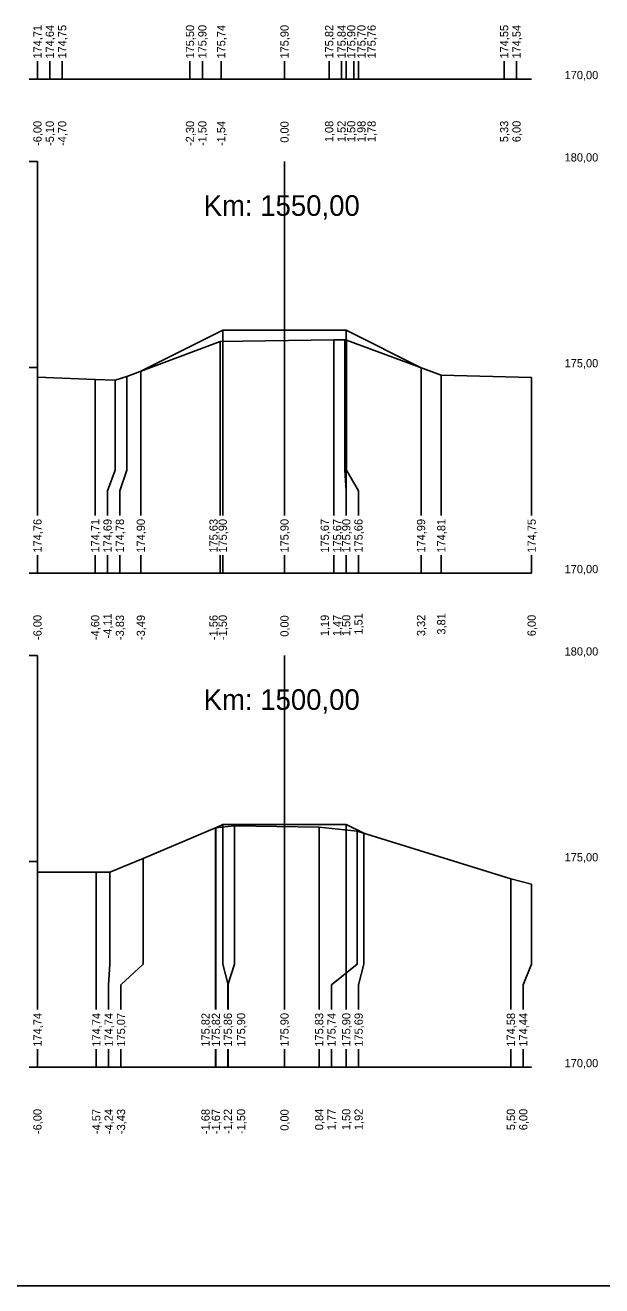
# Model space of a CAD drawing. Extents: x -614174 to -599765, y -1185887 to -1181080.
# Drawn here: x -612606.33 to -612592.33, y -1184252.54 to -1184221.92 of the extents above; entities that cross this region are included whole.
import ezdxf

# ---------------------------------------------------------------- set-up
doc = ezdxf.new("R2010")
doc.units = 0
for name, color, linetype in [('11', 7, 'Continuous'), ('16', 7, 'Continuous'), ('21', 7, 'Continuous'), ('28', 7, 'Continuous'), ('59', 7, 'Continuous'), ('8', 7, 'Continuous'), ('návrh', 7, 'Continuous')]:
    doc.layers.add(name, color=color, linetype=linetype)

msp = doc.modelspace()

# ---------------------------------------------------------------- linework, layer by layer
for points in [[(-612606.029, -1184230.472), (-612604.627, -1184230.528), (-612604.138, -1184230.545), (-612603.86, -1184230.457), (-612601.594, -1184229.606), (-612598.835, -1184229.568), (-612598.561, -1184229.564), (-612598.523, -1184229.576), (-612596.223, -1184230.424), (-612594.029, -1184230.479)], [(-612603.518, -1184230.329), (-612601.53, -1184229.335), (-612600.03, -1184229.335), (-612598.53, -1184229.335), (-612596.714, -1184230.243)], [(-612601.529, -1184229.335), (-612601.53, -1184229.335)], [(-612600.03, -1184229.335), (-612600.03, -1184229.335)], [(-612598.53, -1184229.335), (-612598.53, -1184229.335)], [(-612603.486, -1184230.326), (-612603.49, -1184230.329), (-612603.488, -1184230.329)], [(-612606.029, -1184242.496), (-612604.6, -1184242.496), (-612604.268, -1184242.497), (-612603.458, -1184242.161), (-612601.706, -1184241.418), (-612601.246, -1184241.373), (-612599.189, -1184241.407), (-612598.264, -1184241.497), (-612594.532, -1184242.657), (-612594.029, -1184242.791)], [(-612601.695, -1184241.417), (-612601.53, -1184241.335), (-612600.03, -1184241.335), (-612598.53, -1184241.335), (-612598.107, -1184241.546)], [(-612601.695, -1184241.417), (-612601.695, -1184241.417), (-612601.695, -1184241.417)], [(-612601.53, -1184241.335), (-612601.53, -1184241.335)], [(-612600.03, -1184241.335), (-612600.03, -1184241.335)], [(-612598.53, -1184241.335), (-612598.53, -1184241.335)]]:
    msp.add_lwpolyline(points)
at = {"layer": '11'}
for points in [[(-612606.029, -1184222.794), (-612606.029, -1184223.234)], [(-612605.729, -1184222.794), (-612605.729, -1184223.234)], [(-612605.429, -1184222.794), (-612605.429, -1184223.234)], [(-612602.325, -1184222.794), (-612602.325, -1184223.234)], [(-612602.025, -1184222.794), (-612602.025, -1184223.234)], [(-612601.567, -1184222.794), (-612601.567, -1184223.234)], [(-612600.03, -1184222.794), (-612600.03, -1184223.234)], [(-612598.945, -1184222.794), (-612598.945, -1184223.234)], [(-612598.645, -1184222.794), (-612598.645, -1184223.234)], [(-612598.53, -1184222.794), (-612598.53, -1184223.234)], [(-612598.345, -1184222.794), (-612598.345, -1184223.234)], [(-612598.23, -1184222.794), (-612598.23, -1184223.234)], [(-612594.696, -1184222.794), (-612594.696, -1184223.234)], [(-612594.396, -1184222.794), (-612594.396, -1184223.234)], [(-612601.53, -1184229.335), (-612601.53, -1184232.734), (-612601.53, -1184233.234), (-612601.53, -1184233.835)], [(-612600.03, -1184229.335), (-612600.03, -1184232.734), (-612600.03, -1184233.234), (-612600.03, -1184233.835)], [(-612598.835, -1184229.568), (-612598.835, -1184232.734), (-612598.835, -1184233.234), (-612598.835, -1184233.835)], [(-612598.561, -1184229.564), (-612598.561, -1184232.734), (-612598.535, -1184233.234), (-612598.535, -1184233.835)], [(-612598.53, -1184229.335), (-612598.53, -1184232.734), (-612598.53, -1184233.234), (-612598.53, -1184233.835)], [(-612598.523, -1184229.576), (-612598.523, -1184232.734), (-612598.235, -1184233.234), (-612598.235, -1184233.835)], [(-612601.594, -1184229.606), (-612601.594, -1184232.734), (-612601.594, -1184233.234), (-612601.594, -1184233.835)], [(-612606.029, -1184230.472), (-612606.029, -1184232.734), (-612606.029, -1184233.234), (-612606.029, -1184233.835)], [(-612603.86, -1184230.457), (-612603.86, -1184232.734), (-612604.027, -1184233.234), (-612604.027, -1184233.835)], [(-612603.518, -1184230.329), (-612603.518, -1184232.734), (-612603.518, -1184233.234), (-612603.518, -1184233.835)], [(-612596.714, -1184230.243), (-612596.714, -1184232.734), (-612596.714, -1184233.234), (-612596.714, -1184233.835)], [(-612596.223, -1184230.424), (-612596.223, -1184232.734), (-612596.223, -1184233.234), (-612596.223, -1184233.835)], [(-612594.029, -1184230.479), (-612594.029, -1184232.734), (-612594.029, -1184233.234), (-612594.029, -1184233.835)], [(-612604.627, -1184230.528), (-612604.627, -1184232.734), (-612604.627, -1184233.234), (-612604.627, -1184233.835)], [(-612604.138, -1184230.545), (-612604.138, -1184232.734), (-612604.327, -1184233.234), (-612604.327, -1184233.835)], [(-612606.029, -1184234.794), (-612606.029, -1184235.234)], [(-612604.627, -1184234.794), (-612604.627, -1184235.234)], [(-612604.327, -1184234.794), (-612604.327, -1184235.234)], [(-612604.027, -1184234.794), (-612604.027, -1184235.234)], [(-612603.518, -1184234.794), (-612603.518, -1184235.234)], [(-612601.594, -1184234.794), (-612601.594, -1184235.234)], [(-612601.53, -1184234.794), (-612601.53, -1184235.234)], [(-612600.03, -1184234.794), (-612600.03, -1184235.234)], [(-612598.835, -1184234.794), (-612598.835, -1184235.234)], [(-612598.535, -1184234.794), (-612598.535, -1184235.234)], [(-612598.53, -1184234.794), (-612598.53, -1184235.234)], [(-612598.235, -1184234.794), (-612598.235, -1184235.234)], [(-612596.714, -1184234.794), (-612596.714, -1184235.234)], [(-612596.223, -1184234.794), (-612596.223, -1184235.234)], [(-612594.029, -1184234.794), (-612594.029, -1184235.234)], [(-612601.706, -1184241.418), (-612601.706, -1184244.734), (-612601.706, -1184245.234), (-612601.706, -1184245.835)], [(-612601.695, -1184241.417), (-612601.695, -1184244.734), (-612601.695, -1184245.234), (-612601.695, -1184245.835)], [(-612601.53, -1184241.335), (-612601.53, -1184244.734), (-612601.395, -1184245.234), (-612601.395, -1184245.835)], [(-612601.246, -1184241.373), (-612601.246, -1184244.734), (-612601.406, -1184245.234), (-612601.406, -1184245.835)], [(-612600.03, -1184241.335), (-612600.03, -1184244.734), (-612600.03, -1184245.234), (-612600.03, -1184245.835)], [(-612599.189, -1184241.407), (-612599.189, -1184244.734), (-612599.189, -1184245.234), (-612599.189, -1184245.835)], [(-612598.264, -1184241.497), (-612598.264, -1184244.734), (-612598.889, -1184245.234), (-612598.889, -1184245.835)], [(-612598.53, -1184241.335), (-612598.53, -1184244.734), (-612598.53, -1184245.234), (-612598.53, -1184245.835)], [(-612598.107, -1184241.546), (-612598.107, -1184244.734), (-612598.23, -1184245.234), (-612598.23, -1184245.835)], [(-612603.458, -1184242.161), (-612603.458, -1184244.734), (-612604, -1184245.234), (-612604, -1184245.835)], [(-612606.029, -1184242.496), (-612606.029, -1184244.734), (-612606.029, -1184245.234), (-612606.029, -1184245.835)], [(-612604.6, -1184242.496), (-612604.6, -1184244.734), (-612604.6, -1184245.234), (-612604.6, -1184245.835)], [(-612604.268, -1184242.497), (-612604.268, -1184244.734), (-612604.3, -1184245.234), (-612604.3, -1184245.835)], [(-612594.532, -1184242.657), (-612594.532, -1184244.734), (-612594.532, -1184245.234), (-612594.532, -1184245.835)], [(-612594.029, -1184242.791), (-612594.029, -1184244.734), (-612594.232, -1184245.234), (-612594.232, -1184245.835)], [(-612606.029, -1184246.794), (-612606.029, -1184247.234)], [(-612604.6, -1184246.794), (-612604.6, -1184247.234)], [(-612604.3, -1184246.794), (-612604.3, -1184247.234)], [(-612604, -1184246.794), (-612604, -1184247.234)], [(-612601.706, -1184246.794), (-612601.706, -1184247.234)], [(-612601.695, -1184246.794), (-612601.695, -1184247.234)], [(-612601.406, -1184246.794), (-612601.406, -1184247.234)], [(-612601.395, -1184246.794), (-612601.395, -1184247.234)], [(-612600.03, -1184246.794), (-612600.03, -1184247.234)], [(-612599.189, -1184246.794), (-612599.189, -1184247.234)], [(-612598.889, -1184246.794), (-612598.889, -1184247.234)], [(-612598.53, -1184246.794), (-612598.53, -1184247.234)], [(-612598.23, -1184246.794), (-612598.23, -1184247.234)], [(-612594.532, -1184246.794), (-612594.532, -1184247.234)], [(-612594.232, -1184246.794), (-612594.232, -1184247.234)]]:
    msp.add_lwpolyline(points, dxfattribs=at)
at = {"layer": '16'}
for p, q in [((-612606.029, -1184223.234), (-612594.029, -1184223.234)), ((-612606.029, -1184235.234), (-612594.029, -1184235.234)), ((-612606.029, -1184247.234), (-612594.029, -1184247.234))]:
    msp.add_line(p, q, dxfattribs=at)
for points in [[(-612596.718, -1184230.241), (-612596.714, -1184230.243), (-612596.711, -1184230.244)], [(-612598.107, -1184241.546), (-612598.107, -1184241.546), (-612598.107, -1184241.546)]]:
    msp.add_lwpolyline(points, dxfattribs=at)
at = {"layer": '21'}
for p, q in [((-612606.229, -1184223.234), (-612606.029, -1184223.234)), ((-612606.229, -1184225.234), (-612606.029, -1184225.234)), ((-612606.229, -1184230.234), (-612606.029, -1184230.234)), ((-612606.229, -1184235.234), (-612606.029, -1184235.234)), ((-612606.229, -1184237.234), (-612606.029, -1184237.234)), ((-612606.229, -1184242.234), (-612606.029, -1184242.234)), ((-612606.229, -1184247.234), (-612606.029, -1184247.234))]:
    msp.add_line(p, q, dxfattribs=at)
at = {"layer": '28'}
for p, q in [((-612600.029, -1184223.234), (-612600.029, -1184222.794)), ((-612600.029, -1184233.835), (-612600.029, -1184225.234)), ((-612600.029, -1184235.234), (-612600.029, -1184234.794)), ((-612600.029, -1184245.835), (-612600.029, -1184237.234)), ((-612600.029, -1184247.234), (-612600.029, -1184246.794))]:
    msp.add_line(p, q, dxfattribs=at)
at = {"layer": '8'}
for p, q in [((-612606.029, -1184223.234), (-612606.029, -1184222.794)), ((-612606.029, -1184233.835), (-612606.029, -1184225.234)), ((-612606.029, -1184235.234), (-612606.029, -1184234.794)), ((-612606.029, -1184245.835), (-612606.029, -1184237.234)), ((-612606.029, -1184247.234), (-612606.029, -1184246.794))]:
    msp.add_line(p, q, dxfattribs=at)
at = {"layer": 'návrh'}
msp.add_line((-612607.713, -1184252.543), (-612586.713, -1184252.543), dxfattribs=at)

# ---------------------------------------------------------------- texts
at = {"layer": '16'}
for s, p in [('174,71', (-612605.929, -1184222.734)), ('174,64', (-612605.629, -1184222.734)), ('174,75', (-612605.329, -1184222.734)), ('175,50', (-612602.225, -1184222.734)), ('175,90', (-612601.925, -1184222.734)), ('175,74', (-612601.467, -1184222.734)), ('175,90', (-612599.93, -1184222.734)), ('175,82', (-612598.845, -1184222.734)), ('175,84', (-612598.545, -1184222.734)), ('175,90', (-612598.309, -1184222.734)), ('175,70', (-612598.062, -1184222.734)), ('175,76', (-612597.815, -1184222.734)), ('174,55', (-612594.596, -1184222.734)), ('174,54', (-612594.296, -1184222.734)), ('174,76', (-612605.929, -1184234.734)), ('174,71', (-612604.527, -1184234.734)), ('174,69', (-612604.227, -1184234.734)), ('174,78', (-612603.927, -1184234.734)), ('174,90', (-612603.418, -1184234.734)), ('175,63', (-612601.653, -1184234.734)), ('175,90', (-612601.43, -1184234.734)), ('175,90', (-612599.93, -1184234.734)), ('175,67', (-612598.953, -1184234.734)), ('175,67', (-612598.653, -1184234.734)), ('175,90', (-612598.43, -1184234.734)), ('175,66', (-612598.135, -1184234.734)), ('174,99', (-612596.614, -1184234.734)), ('174,81', (-612596.123, -1184234.734)), ('174,75', (-612593.929, -1184234.734)), ('174,74', (-612605.929, -1184246.734)), ('174,74', (-612604.5, -1184246.734)), ('174,74', (-612604.2, -1184246.734)), ('175,07', (-612603.9, -1184246.734)), ('175,82', (-612601.848, -1184246.734)), ('175,82', (-612601.595, -1184246.734)), ('175,86', (-612601.306, -1184246.734)), ('175,90', (-612600.984, -1184246.734)), ('175,90', (-612599.93, -1184246.734)), ('175,83', (-612599.089, -1184246.734)), ('175,74', (-612598.789, -1184246.734)), ('175,90', (-612598.43, -1184246.734)), ('175,69', (-612598.13, -1184246.734)), ('174,58', (-612594.432, -1184246.734)), ('174,44', (-612594.132, -1184246.734))]:
    msp.add_text(s, height=0.2, rotation=90, dxfattribs=at).set_placement(p)
at = {"layer": '21'}
for s, p in [('170,00', (-612593.229, -1184223.234)), ('180,00', (-612593.229, -1184225.234)), ('175,00', (-612593.229, -1184230.234)), ('170,00', (-612593.229, -1184235.234)), ('180,00', (-612593.229, -1184237.234)), ('175,00', (-612593.229, -1184242.234)), ('170,00', (-612593.229, -1184247.234))]:
    msp.add_text(s, height=0.2, dxfattribs=at).set_placement(p)
at = {"layer": '28'}
for s, p in [('Km: 1550,00', (-612601.993, -1184226.554)), ('Km: 1500,00', (-612601.993, -1184238.554))]:
    msp.add_text(s, height=0.5, dxfattribs=at).set_placement(p)
at = {"layer": '59'}
for s, p in [('-6,00', (-612605.929, -1184224.857)), ('-5,10', (-612605.629, -1184224.857)), ('-4,70', (-612605.329, -1184224.857)), ('-2,30', (-612602.225, -1184224.857)), ('-1,50', (-612601.925, -1184224.857)), ('-1,54', (-612601.467, -1184224.857)), ('0,00', (-612599.93, -1184224.777)), ('1,08', (-612598.845, -1184224.765)), ('1,52', (-612598.545, -1184224.763)), ('1,50', (-612598.309, -1184224.764)), ('1,98', (-612598.062, -1184224.765)), ('1,78', (-612597.815, -1184224.765)), ('5,33', (-612594.596, -1184224.765)), ('6,00', (-612594.296, -1184224.764)), ('-6,00', (-612605.929, -1184236.857)), ('-4,60', (-612604.527, -1184236.857)), ('-4,11', (-612604.227, -1184236.819)), ('-3,83', (-612603.927, -1184236.858)), ('-3,49', (-612603.418, -1184236.858)), ('-1,56', (-612601.653, -1184236.858)), ('-1,50', (-612601.43, -1184236.857)), ('0,00', (-612599.93, -1184236.777)), ('1,19', (-612598.953, -1184236.765)), ('1,47', (-612598.653, -1184236.765)), ('1,50', (-612598.43, -1184236.764)), ('1,51', (-612598.135, -1184236.726)), ('3,32', (-612596.614, -1184236.763)), ('3,81', (-612596.123, -1184236.726)), ('6,00', (-612593.929, -1184236.764)), ('-6,00', (-612605.929, -1184248.857)), ('-4,57', (-612604.5, -1184248.858)), ('-4,24', (-612604.2, -1184248.857)), ('-3,43', (-612603.9, -1184248.858)), ('-1,68', (-612601.848, -1184248.858)), ('-1,67', (-612601.595, -1184248.858)), ('-1,22', (-612601.306, -1184248.856)), ('-1,50', (-612600.984, -1184248.857)), ('0,00', (-612599.93, -1184248.777)), ('0,84', (-612599.089, -1184248.764)), ('1,77', (-612598.789, -1184248.765)), ('1,50', (-612598.43, -1184248.764)), ('1,92', (-612598.13, -1184248.763)), ('5,50', (-612594.432, -1184248.764)), ('6,00', (-612594.132, -1184248.764))]:
    msp.add_text(s, height=0.2, rotation=90, dxfattribs=at).set_placement(p)

doc.saveas('drawing.dxf')
